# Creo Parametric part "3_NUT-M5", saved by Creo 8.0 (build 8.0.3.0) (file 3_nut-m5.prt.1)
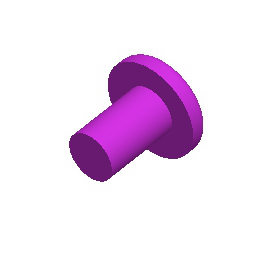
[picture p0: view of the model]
Units: millimeter Newton Second (mmNs); MM, TONNE, SECS

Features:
  1. datum plane "RIGHT"
  2. datum plane "TOP"
  3. datum plane "FRONT"
  4. coordinate system
  5. protrusion
  6. cut

Layers: 0_ALL_AXIS, 0_ALL_CSYS, 0_ALL_CURVES, 0_ALL_PLANES, 0_ALL_POINTS, 0_ALL_SURFS, NUT-M5

Surfaces: 16 plane, 4 cylinder, 2 torus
